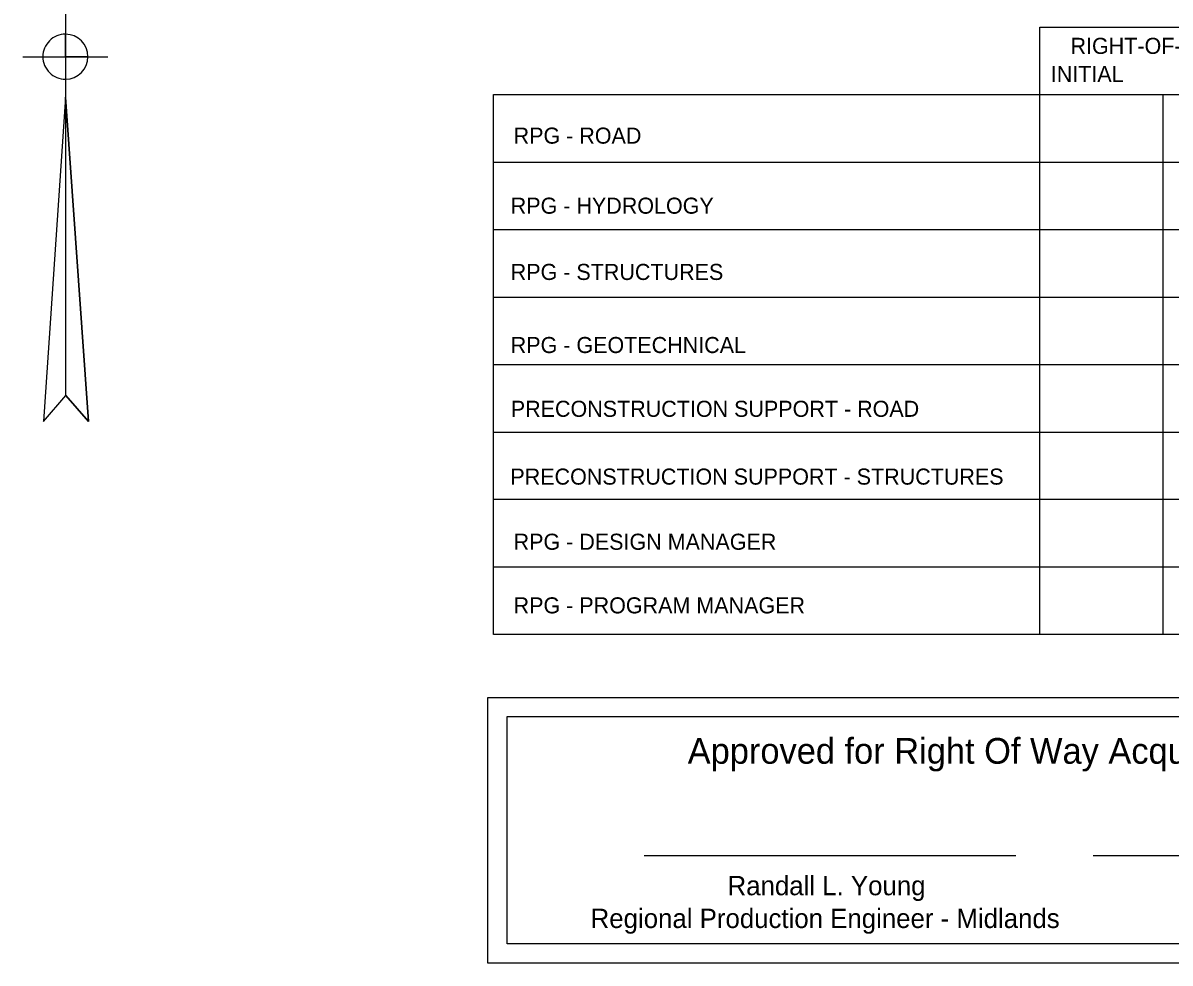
# Model space of a CAD drawing. Extents: x -796 to 2793, y -4650 to 4425.
# Drawn here: x 2239.3 to 2596, y 1239.1 to 1531.5 of the extents above; entities that cross this region are included whole.
import ezdxf

# ---------------------------------------------------------------- set-up
doc = ezdxf.new("R2010")
doc.units = 0
for name, color, linetype in [('RD_EX_Misc', 7, 'Continuous'), ('RD_HC_Data', 7, 'Continuous'), ('RD_HC_Data_Tic', 7, 'Continuous'), ('RD_SHT_Bndy', 7, 'Continuous')]:
    doc.layers.add(name, color=color, linetype=linetype)

msp = doc.modelspace()

# ---------------------------------------------------------------- linework, layer by layer
at = {"layer": 'RD_EX_Misc'}
for p, q in [((2252.53, 1626.13), (2252.53, 1415.43)), ((2239.28, 1521.03), (2265.68, 1521.03)), ((2252.53, 1508.43), (2245.63, 1407.58)), ((2252.53, 1508.43), (2259.63, 1407.58)), ((2245.63, 1407.58), (2252.58, 1415.63)), ((2259.63, 1407.58), (2252.58, 1415.63))]:
    msp.add_line(p, q, dxfattribs=at)
for points in [[(2252.53, 1521.03), (2252.53, 1528.03)], [(2245.48, 1521.03), (2252.53, 1521.03)], [(2252.53, 1521.03), (2252.53, 1514.03)], [(2259.48, 1521.03), (2252.53, 1521.03)], [(2252.53, 1508.43), (2252.53, 1415.57), (2252.58, 1415.63), (2259.63, 1407.58), (2252.53, 1508.43)]]:
    msp.add_lwpolyline(points, dxfattribs=at)
for start, end in [(89.5907, 180), (89.5907, 180), (0, 89.5907), (180, 270.4093), (270.4093, 0), (270.4093, 0)]:
    msp.add_arc((2252.48, 1521.03), 7, start, end, dxfattribs=at)
at = {"layer": 'RD_HC_Data'}
for p, q in [((2555.5, 1341.28), (2555.5, 1530.23)), ((2555.5, 1530.23), (2700.45, 1530.23)), ((2385.55, 1509.23), (2700.45, 1509.23)), ((2385.55, 1341.28), (2385.55, 1509.23)), ((2593.75, 1509.23), (2593.75, 1341.28)), ((2385.55, 1488.23), (2700.45, 1488.23)), ((2385.55, 1467.23), (2700.45, 1467.23)), ((2385.55, 1446.23), (2700.45, 1446.23)), ((2700.45, 1425.23), (2385.55, 1425.23)), ((2385.55, 1404.23), (2700.45, 1404.23)), ((2700.45, 1383.28), (2385.55, 1383.28)), ((2700.45, 1362.28), (2385.55, 1362.28)), ((2700.45, 1341.28), (2385.55, 1341.28)), ((2432.41, 1272.52), (2547.96, 1272.52)), ((2572.08, 1272.52), (2646.22, 1272.52))]:
    msp.add_line(p, q, dxfattribs=at)
for points in [[(2383.87, 1321.76), (2702.13, 1321.76), (2702.13, 1239.11), (2383.87, 1239.11)], [(2389.87, 1315.76), (2696.13, 1315.76), (2696.13, 1245.11), (2389.87, 1245.11)]]:
    msp.add_lwpolyline(points, close=True, dxfattribs=at)

# ---------------------------------------------------------------- texts
at = {"layer": 'RD_HC_Data_Tic'}
for s, p in [('RIGHT-OF-WAY', (2565.01, 1521.9)), ('INITIAL', (2558.87, 1513.15))]:
    msp.add_text(s, height=4.998, rotation=360, dxfattribs=at).set_placement(p)
for s, height, p in [('RPG - ROAD', 4.998, (2391.85, 1493.98)), ('RPG - HYDROLOGY ', 4.998, (2390.95, 1472.19)), ('RPG - STRUCTURES', 4.998, (2390.95, 1451.58)), ('RPG - GEOTECHNICAL', 4.998, (2390.95, 1428.85)), ('PRECONSTRUCTION SUPPORT - ROAD', 4.998, (2390.97, 1409.01)), ('PRECONSTRUCTION SUPPORT - STRUCTURES', 4.998, (2390.84, 1387.92)), ('RPG - DESIGN MANAGER', 4.998, (2391.85, 1367.66)), ('RPG - PROGRAM MANAGER', 4.998, (2391.85, 1347.87)), ('Approved for Right Of Way Acquisition:', 8, (2445.98, 1301.11))]:
    msp.add_text(s, height=height, dxfattribs=at).set_placement(p)
at = {"layer": 'RD_SHT_Bndy'}
for s, p in [('Randall L. Young', (2458.37, 1260.2)), ('Regional Production Engineer - Midlands', (2415.8, 1250.01))]:
    msp.add_text(s, height=6, dxfattribs=at).set_placement(p)

doc.saveas('drawing.dxf')
